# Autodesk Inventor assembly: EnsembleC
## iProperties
Author: Administrateur
Created: 2002-04
Part Number: EnsembleC
Document SubType Name: Assemblage
Designer: Administrateur
Control State: 0
Master: False
Checked Out: False
PropertySet Name: Design Tracking Control
Shininess: 41.0
Angle Display Precision: 2
Document Length Units: 11269
Document Angle Units: 11283
Document Time Units: 11279
Document Mass Units: 11290
Document Length Units Precision: 3
Document Angle Units Precision: 2
Compacted: False
PropertySet Name: _Private Model Information
Density: 0.0
Volumn: 0.0
Area: 0.0
PropertySet Name: Model Information
